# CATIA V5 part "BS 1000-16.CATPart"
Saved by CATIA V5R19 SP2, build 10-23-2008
Part number: BS 1000-16
Bounding box of the stored display mesh (mm): x -24.865 to 24.865, y -24.997 to 24.997, z 0 to 70
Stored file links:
  C:\Users\Bora\Desktop\3D Katı model\BS serisi\BS 1000\BS 1000-16.CATPart
  C:\Program Files\Dassault Systemes\B19\intel_a\reffiles\standard\MetricThickPitch.txt
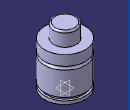
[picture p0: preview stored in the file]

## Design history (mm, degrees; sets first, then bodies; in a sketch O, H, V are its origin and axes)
Body1 (main body)
  Sketch1 on yz-plane, origin (0, 0, 0), H (0, 1, 0), V (0, 0, 1)
    point P2 (14, 68)
    line L1 (14, 68) -> (14, 53)
    point P3 (25, 40.5)
    line L2 (25, 53) -> (25, 40.5)
    point P6 (25, 36.5)
    line L3 (25, 36.5) -> (25, 7.5)
    line L4 (25, 4) -> (25, 0)
    point P9 (25, 36.5)
    point P10 (25, 40.5)
    arc A1 centre (25, 38.5) radius 2 from (25, 40.5) to (25, 36.5) ccw
    point P12 (14, 68)
    arc A2 centre (12, 68) radius 2 from (14, 68) to (12, 70) ccw
    point P13 (22.5, 4)
    point P14 (22.5, 4)
    line L5 (22.5, 7.5) -> (22.5, 4)
    line L6 (12, 70) -> (0, 70)
    point P16 (0, 70)
    line L7 (14, 53) -> (25, 53)
    line L8 (0, 0) -> (25, 0)
    line L9 (22.5, 7.5) -> (25, 7.5)
    line L10 (22.5, 4) -> (25, 4)
    coincidence: P16 V, P2 P12, P3 P10, P6 P9, P13 P14
    tangency: L6 A2
    horizontal: L7 H, L8 H, L9 H, L10 H
  Shaft1: profile Sketch1, axis Sketch1.V, angle 360
  Sketch2 on face of Shaft1 from Sketch1.L8, origin (0, 0, 0), H (1, 0, 0), V (0, -1, 0)
    point P1 (10, 0)
    distance P1 V = 10
  Hole1: placed by Sketch2, at (10, 0, 0) direction (0, 0, 1), diameter 6.647, depth 6, threaded "M8", thread diameter 8, thread depth 6, pitch 1.25
  CircPattern1: of Hole1, instances 2, angular step 180, axis from xy-plane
